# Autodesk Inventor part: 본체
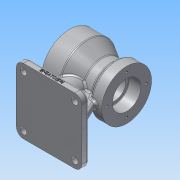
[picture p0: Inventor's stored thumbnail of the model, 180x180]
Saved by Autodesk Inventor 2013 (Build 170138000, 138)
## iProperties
Created: 2019-01
Part Number: 본체
Material: 알루미늄 6061
Document SubType Name: Modeling
Designer: Administrator
Mass: 902.255 g
Surface Area: 603.246 cm^2
Volume: 332.935 cm^3
Density: 2.71 g/cm^3
Author: Administrator
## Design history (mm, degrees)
sketch "스케치1"
  geometry: L1 (0, 0)-(80, 0); L2 (0, 40)-(25, 40); L3 (25, 40)-(45.785, 28); L4 (45.785, 28)-(59.126, 28); L5 (59.126, 28)-(65, 35); L6 (65, 35)-(80, 35); L7 (80, 35)-(80, 0); L8 (0, 40)-(0, 0)
  constraints: 16 end point, 4 parallel, 2 vertical alignment, 1 horizontal, 1 perpendicular
  dimensions: "d0" = 80 distance of L1.start L1.end; "d1" = 80 diameter of L2 L1; "d2" = 70 diameter of L6 L1; "d3" = 56 diameter of L4 L1; "d4" = 30 deg angle of L4 L3; "d5" = 50 deg angle of L4 L5; "d6" = 25 distance of L2.start L2.end; "d7" = 15 distance of L5.end L6.end
revolve "회전1" sketch "스케치1" stored, may be unused: angle "d8" = 90 deg
sketch "스케치2"
  geometry: C1 r 40 at (0, 0) reference; C2 r 26 at (0, 0)
  constraints: 1 centre point, 1 coincident
  dimensions: "d9" = 52 diameter of C2
extrude "돌출1" cut sketch "스케치2" distance "d10" = 20; taper "d11" = 0 deg
fillet "모깎기1" dims "d12" = 1
sketch "스케치4"
  geometry: C1 r 35 at (0, 0) reference; C2 r 20 at (0, 0)
  constraints: 1 centre point, 1 coincident
  dimensions: "d13" = 40 diameter of C2
extrude "돌출2" cut sketch "스케치4" distance "d14" = 17; taper "d15" = 0 deg
fillet "모깎기2" dims "d16" = 0.6
sketch "스케치5"
  geometry: C1 r 25 at (0, 0) reference; C2 r 16 at (0, 0)
  constraints: 1 centre point, 1 coincident
  dimensions: "d17" = 32 diameter of C2
extrude "돌출3" cut sketch "스케치5" stored distance "d18" = 17; taper "d19" = 0 deg
sketch "스케치6" dims "d20" = 66
  geometry: C1 r 40 at (0, 0) reference; 2 further points
  constraints: 2 vertical alignment, 1 coincident, 2 other
hole "구멍1" sketch "스케치6" at (0, 33) diameter "d21" = 3.459; stored, may be unused: countersink angle "d25" = 90 deg, drill point angle "d27" = 118 deg; dims "d22" = 9, "d23" = 4, "d24" = 2, "d26" = 11
node "작업축1"
sketch "스케치7" dims "d31" = 55
  geometry: C1 r 35 at (0, 0) reference; 2 further points
  constraints: 2 vertical alignment, 1 coincident, 2 other
hole "구멍2" sketch "스케치7" at (0, 27.5) diameter "d32" = 3.459; stored, may be unused: countersink angle "d36" = 90 deg, drill point angle "d38" = 118 deg; dims "d33" = 9, "d34" = 4, "d35" = 2, "d37" = 11
fillet "모깎기3" dims "d42" = 3
node "작업 평면1"
sketch "스케치8"
  geometry: L1 (-5, -46)-(-97, -46); L2 (-5, 46)-(-97, 46); L3 (-5, -46)-(-5, 46); L4 (-97, -46)-(-97, 46); 3 further points
  constraints: 8 end point, 2 horizontal alignment, 2 midpoint, 1 parallel, 1 perpendicular
  dimensions: "d49" = 5 distance from line of L3 point (0, 0); "d50" = 92 distance between parallel lines of L3 L4; "d51" = 92 distance between parallel lines of L2 L1
extrude "돌출4" join sketch "스케치8" distance "d52" = 10; taper "d53" = 0 deg
fillet "모깎기4" dims "d54" = 10
sketch "스케치9"
  geometry: A1 r 10 centre (87, 36) between (97, 36) and (87, 46) reference; A2 r 10 centre (15, 36) between (15, 46) and (5, 36) reference; A3 r 10 centre (15, -36) between (5, -36) and (15, -46) reference; A4 r 10 centre (87, -36) between (87, -46) and (97, -36) reference; 5 further points
  constraints: 4 coincident
hole "구멍3" sketch "스케치9" at (15, 36), (87, 36), (87, -36), (15, -36) diameter "d55" = 9; stored, may be unused: countersink angle "d59" = 90 deg, drill point angle "d61" = 118 deg; dims "d56" = 9, "d57" = 4, "d58" = 2, "d60" = 11
fillet "모깎기5" dims "d62" = 3
sketch "스케치10"
  geometry: L1 (5, 36)-(5, -36) reference; C1 r 16 at (35, 0); 1 further point
  constraints: 1 centre point, 1 horizontal alignment
  dimensions: "d63" = 32 diameter of C1; "d64" = 30 distance from line of L1 C1.centre
extrude "돌출5" join sketch "스케치10" stored distance "d65" = 10; taper "d66" = 0 deg
sketch "스케치11"
  geometry: L1 (82.5, -70)-(91.5, -70) reference; L2 (15, -70)-(87, -70) reference; L3 (66.399, -35)-(80, -35) reference; L4 (60.026, -29.072)-(64.101, -33.928) reference; L5 (51, -28)-(57.727, -28) reference; L6 (51, -70)-(51, -28) reference; L7 (70.679, -35)-(87, -70); L8 (97, -73)-(97, -80) reference; A1 r 3 centre (66.399, -32) between (64.101, -33.928) and (66.399, -35) reference; A2 r 3 centre (57.727, -31) between (60.026, -29.072) and (57.727, -28) reference; 1 further point
  constraints: 2 end point, 1 midpoint, 1 point on line
  dimensions: "d67" = 10 distance from line of L8 L7.end; "d68" = 25 deg angle of L8 L7
feature "리브1" sketch "스케치11" dims "d69" = 1, "d70" = 10, "d71" = 0, "d72" = 0, "d73" = 1, "d74" = 1
fillet "모깎기6" dims "d75" = 3
fillet "모깎기7" dims "d76" = 3
sketch "스케치12"
  geometry: L1 (72, 0)-(0, 0) reference; L2 (-10, 7)-(-10, 0) reference; 2 further points
  constraints: 1 other
  dimensions: "d77" = 46 distance from line of L2 point (36, 4); "d78" = 4 distance from line of L1 point (36, 4)
feature "엠보싱1" sketch "스케치12" dims "d79" = 0.5, "d80" = 0
node "솔리드1"
pattern_circular "원형 패턴1" dims angle "d29" = 360 deg
pattern_circular "원형 패턴2" dims angle "d40" = 360 deg
